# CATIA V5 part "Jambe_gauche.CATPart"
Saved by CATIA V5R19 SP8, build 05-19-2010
Part number: Jambe_gauche
Bounding box of the stored display mesh (mm): x -895 to -651.003, y -2625 to -1075, z -150 to 190
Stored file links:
  G:\EU_thinkMotion\CFAO_2010\MMS_groupe2\MMS_groupe2\OK\mmartini\mmartiniCFAO\Jambe_gauche.CATPart
  C:\Users\Mathieu Martini\Desktop\CFAO\Animation\CFAO.CATProduct
  G:\EU_thinkMotion\CFAO_2010\MMS_groupe2\MMS_groupe2\OK\mmartini\mmartiniCFAO\Squelette.CATPart
  G:\EU_thinkMotion\CFAO_2010\MMS_groupe2\MMS_groupe2\OK\mmartini\mmartiniCFAO\Raccord_jambe_gauche_berceau.CATPart
  G:\EU_thinkMotion\CFAO_2010\MMS_groupe2\MMS_groupe2\OK\mmartini\mmartiniCFAO\Jambe_droite.CATPart
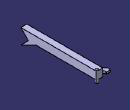
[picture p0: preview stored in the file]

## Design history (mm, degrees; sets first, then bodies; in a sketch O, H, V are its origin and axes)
External parameters (linked from other documents)
  External.diametre_canon = 150 mm
  External.diametre_verin = 120 mm
AxisSystem1: origin (0, 0, 0), X (1, 0, 0), Y (0, 1, 0), Z (0, 0, 1)
Set1
  Sketch1 on Plane1, origin (-675, 0, 0), H (0, 1, 0), V (0, 0, 1)
    line L1 (-2475, 150) -> (-1125, 150)
    line L2 (-1125, 150) -> (-1125, 0)
    line L3 (-1125, 0) -> (-2475, 0)
    line L4 (-2475, 0) -> (-2475, 150)
    reference projected point E1 (-900, 150) from Line1
    reference projected point E2 (-900, 150) from Line1
    distance L2 E1 = 225 {= External.diametre_canon *1.5}
    distance L3 L1 = 150 {= External.diametre_canon}
    distance L4 L2 = 1350 {= External.diametre_canon *9}
    horizontal: L1 H, L3 H
    vertical: L2 V, L4 V
    coincidence: L1 E2
Set2
  Plane1 "Plan_verin_gauche": linked copy from another document
  Line1 "axe_berceau_jambe": linked copy from another document
  DatumCurve1: linked copy from another document
Body1 (main body)
  Pad1: profile Sketch1, direction (-1, 0, 0), length 120 {= External.diametre_verin}
  Sketch2 on face of Pad1 from Sketch1.L2, origin (0, -1125, 0), H (-1, 0, 0), V (0, 0, 1)
    line L1 (675, 190) -> (699, 190)
    line L2 (699, 190) -> (699, -40)
    line L3 (699, -40) -> (675, -40)
    line L4 (675, -40) -> (675, 190)
    reference projected line E1 (675, 150) -> (795, 150) from edge [face of Pad1 from Sketch1.L2 | face of Pad1 from Sketch1.L1]
    reference projected line E2 (675, 0) -> (675, 150) from edge [face of Pad1 from Sketch1.L2 | start face of Pad1]
    reference projected line E3 (675, 0) -> (795, 0) from edge [face of Pad1 from Sketch1.L3 | face of Pad1 from Sketch1.L2]
    distance E1 L1 = 40 {= External.diametre_verin /3}
    distance L3 E3 = 40 {= External.diametre_verin /3}
    distance L4 L2 = 24 {= External.diametre_verin /5}
    horizontal: L1 H, L3 H
    vertical: L2 V, L4 V
    coincidence: E2 L4
  Shaft1: profile Sketch2, axis edge of DatumCurve1, angle 360
  Sketch3 on face of Pad1 from Sketch1.L1, origin (0, 0, 150), H (1, 0, 0), V (0, 1, 0)
    construction line L1 (-766.4837, -1075) -> (-900.4431, -1075)
    reference projected line E1 (-675, -1125) -> (-795, -1125) from edge [face of Pad1 from Sketch1.L2 | face of Pad1 from Sketch1.L1]
    line L2 (-820, -1075) -> (-895, -1075)
    point P3 (-820, -1075)
    point P5 (-795, -1075)
    axis line L3 (-795, -1185.4224) -> (-795, -1086.1356)
    reference projected line E2 (-795, -1125) -> (-795, -2475) from edge [end face of Pad1 | face of Pad1 from Sketch1.L1]
    line L4 (-795, -1125) -> (-795, -1225)
    point P8 (-795, -1125)
    point P9 (-795, -1225)
    line L5 (-895, -1075) -> (-895, -1125)
    reference projected line E3 (-675, -1125) -> (-795, -1125) from edge [face of Pad1 from Sketch1.L3 | face of Pad1 from Sketch1.L2]
    line L6 (-795, -1225) -> (-895, -1125)
    line L7 (-820, -1075) -> (-820, -1100)
    arc A1 centre (-795, -1100) radius 25 from (-820, -1100) to (-795, -1125) ccw
    point P11 (-795, -1100)
    reference projected line E4 (-675, -1125) -> (-795, -1125) from edge [face of Pad1 from Sketch1.L2 | face of Pad1 from Sketch1.L1]
    point P13 (-795, -1125)
    distance L1 E1 = 50 {= External.diametre_canon /3}
    distance L2 P9 = 150 {= External.diametre_canon}
    distance P5 E3 = 50 {= External.diametre_canon /3}
    length L2 = 75 {= External.diametre_canon /2}
    length L5 = 50 {= External.diametre_canon /3}
    radius A1 = 25 {= External.diametre_canon /6}
    horizontal: L1 H, L2 H
    coincidence: P3 L1, L3 E2, P5 L3, P8 L3, P11 L3, L3 P13, P8 P13
    vertical: L3 V, L4 V, L5 V, L7 V
    tangency: A1 L7, A1 E4
  Sketch4 on end face of Pad1, origin (-795, 0, 0), H (0, -1, 0), V (0, 0, 1)
    axis line L1 (1122.5732, 75) -> (1281.4672, 75)
    reference projected line E1 (1125, 150) -> (2475, 150) from edge [end face of Pad1 | face of Pad1 from Sketch1.L1]
    line L2 (1075, 93.75) -> (1075, 56.25)
    point P3 (1075, 93.75)
    line L3 (1075, 93.75) -> (1225, 112.5)
    point P5 (1225, 112.5)
    line L4 (1225, 112.5) -> (1225, 37.5)
    line L5 (1225, 37.5) -> (1075, 56.25)
    reference projected line E2 (1125, 0) -> (1125, 150) from edge [end face of Pad1 | face of Pad1 from Sketch1.L2]
    distance L1 E1 = 75 {= External.diametre_canon /2}
    distance E2 L2 = 50 {= External.diametre_canon /3}
    length L2 = 37.5 {= External.diametre_canon /4}
    distance L1 P3 = 18.75 {= External.diametre_canon /8}
    length L4 = 75 {= External.diametre_canon /2}
    distance L1 P5 = 37.5 {= External.diametre_canon /4}
    distance L2 L4 = 150 {= External.diametre_canon}
    horizontal: L1 H
    vertical: L2 V, L4 V
  SolidCombine1: FirstComponentProfile Sketch3, FirstComponentDirection Sketch3, SecondComponentProfile Sketch4, SecondComponentDirection Sketch4
  Sketch5 on start face of Pad1, origin (-675, 0, 0), H (0, 1, 0), V (0, 0, 1)
    line L1 (-2475, 0) -> (-2625, -150)
    point P1 (-2475, 0)
    reference projected line E1 (-2475, 150) -> (-2475, 0) from edge [face of Pad1 from Sketch1.L4 | start face of Pad1]
    reference projected line E2 (-2475, 0) -> (-1125, 0) from edge [face of Pad1 from Sketch1.L3 | start face of Pad1]
    line L2 (-2475, 0) -> (-2625, 150)
    point P3 (-2625, 150)
    reference projected line E3 (-1125, 150) -> (-2475, 150) from edge [face of Pad1 from Sketch1.L1 | start face of Pad1]
    line L3 (-2625, 150) -> (-2475, 150)
    point P4 (-2475, 150)
    reference projected point E4 (-2475, 150) from vertex [face of Pad1 from Sketch1.L1 | start face of Pad1 | face of Pad1 from Sketch1.L4]
    line L4 (-2475, 150) -> (-2475, 0)
    line L5 (-2625, -150) -> (-2325, 0)
    point P5 (-2325, 0)
    line L6 (-2325, 0) -> (-2475, 0)
    length L1 V = 150 {= External.diametre_canon}
    length L1 H = 150 {= External.diametre_canon}
    length L6 = 150 {= External.diametre_canon}
    coincidence: E1 P1, P1 E2, P3 E3, E4 P4, P5 H
    perpendicularity: L2 L1
    horizontal: L3 H, L6 H
    vertical: L4 V
  Pad2: profile Sketch5, direction (1, 0, 0), up to end face of Pad1
  Point1: (0, 0, 0), relative to vertex [face of Pad2 from Sketch5.L1 | face of Pad1 | face of Pad2 from Sketch5.L2], in AxisSystem1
